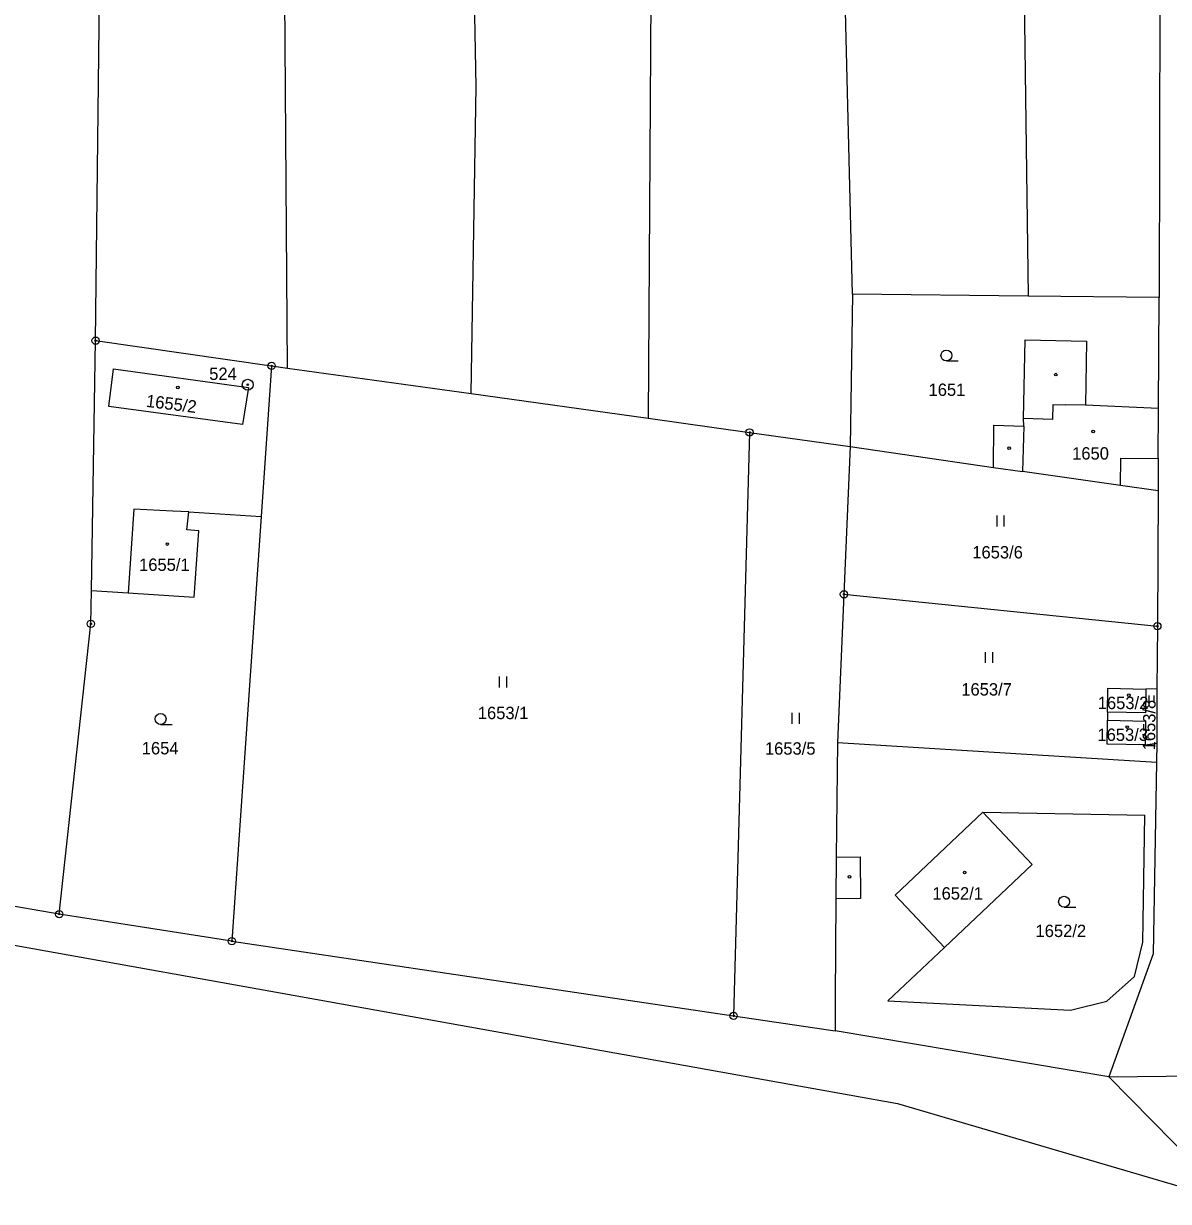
# Model space of a CAD drawing. Extents: x -763296 to -761805, y -1153670 to -1152034.
# Drawn here: x -762912.8 to -762755.5, y -1152914.5 to -1152752.7 of the extents above; entities that cross this region are included whole.
import ezdxf

# ---------------------------------------------------------------- set-up
doc = ezdxf.new("R2010")
doc.units = 0
for name, color, linetype in [('Vrstva 1', 7, 'Continuous'), ('Vrstva 13', 7, 'Continuous'), ('Vrstva 17', 7, 'Continuous'), ('Vrstva 18', 7, 'Continuous'), ('Vrstva 19', 7, 'Continuous'), ('Vrstva 24', 7, 'Continuous'), ('Vrstva 25', 7, 'Continuous'), ('Vrstva 4', 7, 'Continuous'), ('Vrstva 6', 7, 'Continuous')]:
    doc.layers.add(name, color=color, linetype=linetype)

msp = doc.modelspace()

# ---------------------------------------------------------------- linework, layer by layer
at = {"layer": 'Vrstva 1'}
for p, q in [((-762756.58, -1152655.62), (-762756.75, -1152790.35)), ((-762798.9, -1152789.86), (-762799.23, -1152810.81)), ((-762774.75, -1152790.14), (-762798.9, -1152789.86)), ((-762756.75, -1152790.35), (-762774.75, -1152790.14)), ((-762756.85, -1152805.56), (-762756.75, -1152790.35)), ((-762903.46, -1152830.57), (-762902.89, -1152796.26)), ((-762902.89, -1152796.26), (-762878.71, -1152799.72)), ((-762775.39, -1152806.97), (-762775.16, -1152796.14)), ((-762775.16, -1152796.14), (-762766.75, -1152796.35)), ((-762766.75, -1152796.35), (-762766.91, -1152805.13)), ((-762901.08, -1152805.31), (-762900.41, -1152800.13)), ((-762900.41, -1152800.13), (-762881.87, -1152802.7)), ((-762878.71, -1152799.72), (-762880.14, -1152820.4)), ((-762878.71, -1152799.72), (-762876.51, -1152800.03)), ((-762876.51, -1152800.03), (-762851.31, -1152803.53)), ((-762881.87, -1152802.7), (-762882.72, -1152807.79)), ((-762851.31, -1152803.53), (-762826.97, -1152806.92)), ((-762882.72, -1152807.79), (-762901.08, -1152805.31)), ((-762756.85, -1152805.56), (-762766.91, -1152805.13)), ((-762826.97, -1152806.92), (-762813.05, -1152808.86)), ((-762775.38, -1152807.99), (-762775.39, -1152806.97)), ((-762756.9, -1152812.44), (-762756.85, -1152805.56)), ((-762779.53, -1152813.66), (-762779.47, -1152807.88)), ((-762779.47, -1152807.88), (-762775.38, -1152807.99)), ((-762813.05, -1152808.86), (-762815.24, -1152888.99)), ((-762813.05, -1152808.86), (-762799.23, -1152810.81)), ((-762799.23, -1152810.81), (-762800.08, -1152831.1)), ((-762799.23, -1152810.81), (-762779.53, -1152813.66)), ((-762756.9, -1152812.44), (-762756.93, -1152816.89)), ((-762779.53, -1152813.66), (-762775.55, -1152814.21)), ((-762762.09, -1152816.15), (-762775.55, -1152814.21)), ((-762756.93, -1152816.89), (-762762.09, -1152816.15)), ((-762756.93, -1152816.89), (-762757.02, -1152835.47)), ((-762890.36, -1152822.25), (-762890.1, -1152819.76)), ((-762890.1, -1152819.76), (-762880.14, -1152820.4)), ((-762880.14, -1152820.4), (-762884.17, -1152878.73)), ((-762888.71, -1152822.36), (-762890.36, -1152822.25)), ((-762889.33, -1152831.49), (-762888.71, -1152822.36)), ((-762903.54, -1152835.16), (-762903.46, -1152830.57)), ((-762903.46, -1152830.57), (-762898.43, -1152830.91)), ((-762898.43, -1152830.91), (-762889.33, -1152831.49)), ((-762800.08, -1152831.1), (-762800.95, -1152851.46)), ((-762800.08, -1152831.1), (-762757.02, -1152835.47)), ((-762907.88, -1152875.02), (-762903.54, -1152835.16)), ((-762757.02, -1152835.47), (-762757.07, -1152844.07)), ((-762763.87, -1152847.27), (-762763.82, -1152843.98)), ((-762763.82, -1152843.98), (-762758.6, -1152844.12)), ((-762758.6, -1152844.12), (-762758.66, -1152847.39)), ((-762757.07, -1152844.07), (-762758.6, -1152844.12)), ((-762757.07, -1152844.07), (-762757.11, -1152851.54)), ((-762763.87, -1152847.27), (-762763.88, -1152848.38)), ((-762758.66, -1152847.39), (-762763.87, -1152847.27)), ((-762763.93, -1152851.67), (-762763.88, -1152848.38)), ((-762763.88, -1152848.38), (-762758.65, -1152848.51)), ((-762758.65, -1152848.51), (-762758.7, -1152851.79)), ((-762800.95, -1152851.46), (-762801.13, -1152867.18)), ((-762800.95, -1152851.46), (-762757.12, -1152854.17)), ((-762758.7, -1152851.79), (-762763.93, -1152851.67)), ((-762758.7, -1152851.79), (-762757.11, -1152851.54)), ((-762757.11, -1152851.54), (-762757.12, -1152854.17)), ((-762757.12, -1152854.17), (-762757.58, -1152880.46)), ((-762780.99, -1152861.02), (-762774.2, -1152868.19)), ((-762780.99, -1152861.02), (-762758.75, -1152861.44)), ((-762759, -1152878.87), (-762758.75, -1152861.44)), ((-762801.13, -1152867.18), (-762801.17, -1152872.9)), ((-762774.2, -1152868.19), (-762786.25, -1152879.59)), ((-762907.88, -1152875.02), (-762921.7, -1152872.64)), ((-762801.17, -1152872.9), (-762801.28, -1152886.59)), ((-762884.17, -1152878.73), (-762907.88, -1152875.02)), ((-762884.17, -1152878.73), (-762815.24, -1152888.99)), ((-762786.25, -1152879.59), (-762794.03, -1152886.95)), ((-762760.18, -1152883.57), (-762759, -1152878.87)), ((-762757.58, -1152880.46), (-762763.69, -1152897.37)), ((-762763.95, -1152886.97), (-762760.18, -1152883.57)), ((-762801.28, -1152886.59), (-762801.3, -1152891.07)), ((-762794.03, -1152886.95), (-762768.97, -1152888.21)), ((-762768.97, -1152888.21), (-762763.95, -1152886.97)), ((-762815.24, -1152888.99), (-762801.3, -1152891.07)), ((-762763.69, -1152897.37), (-762801.3, -1152891.07)), ((-762763.69, -1152897.37), (-762739.05, -1152897.03))]:
    msp.add_line(p, q, dxfattribs=at)
at = {"layer": 'Vrstva 13'}
for p, q in [((-762956.53, -1152871.69), (-762792.7, -1152901.01)), ((-762792.7, -1152901.01), (-762746.86, -1152914.48))]:
    msp.add_line(p, q, dxfattribs=at)
at = {"layer": 'Vrstva 24'}
for centre, radius in [((-762902.89, -1152796.26), 0.5), ((-762902.89, -1152796.26), 0.1), ((-762878.71, -1152799.72), 0.5), ((-762878.71, -1152799.72), 0.1), ((-762881.99, -1152802.31), 0.75), ((-762881.99, -1152802.31), 0.1), ((-762813.05, -1152808.86), 0.5), ((-762813.05, -1152808.86), 0.1), ((-762800.08, -1152831.1), 0.5), ((-762800.08, -1152831.1), 0.1), ((-762903.54, -1152835.16), 0.5), ((-762903.54, -1152835.16), 0.1), ((-762757.02, -1152835.47), 0.5), ((-762757.02, -1152835.47), 0.1), ((-762907.88, -1152875.02), 0.5), ((-762907.88, -1152875.02), 0.1), ((-762884.17, -1152878.73), 0.5), ((-762884.17, -1152878.73), 0.1), ((-762815.24, -1152888.99), 0.5), ((-762815.24, -1152888.99), 0.1)]:
    msp.add_circle(centre, radius, dxfattribs=at)
at = {"layer": 'Vrstva 25'}
for p, q in [((-762786, -1152799.05), (-762784.4, -1152799.05)), ((-762779.05, -1152821.78), (-762779.05, -1152820.28)), ((-762778.05, -1152821.78), (-762778.05, -1152820.28)), ((-762780.64, -1152840.52), (-762780.64, -1152839.02)), ((-762779.64, -1152840.52), (-762779.64, -1152839.02)), ((-762847.41, -1152843.9), (-762847.41, -1152842.4)), ((-762846.41, -1152843.9), (-762846.41, -1152842.4)), ((-762758.125, -1152846.02), (-762758.125, -1152845.015)), ((-762757.455, -1152846.02), (-762757.455, -1152845.015)), ((-762807.19, -1152848.88), (-762807.19, -1152847.38)), ((-762806.19, -1152848.88), (-762806.19, -1152847.38)), ((-762893.96, -1152848.97), (-762892.36, -1152848.97)), ((-762769.84, -1152874.07), (-762768.24, -1152874.07))]:
    msp.add_line(p, q, dxfattribs=at)
for centre, radius in [((-762786, -1152798.3), 0.75), ((-762770.98, -1152800.92), 0.175), ((-762891.59, -1152802.69), 0.175), ((-762765.83, -1152808.74), 0.175), ((-762777.37, -1152811.03), 0.175), ((-762893.04, -1152824.2), 0.175), ((-762760.93, -1152844.94), 0.175), ((-762893.96, -1152848.22), 0.75), ((-762761.17, -1152849.33), 0.175), ((-762799.32, -1152869.89), 0.175), ((-762783.5, -1152869.31), 0.175), ((-762769.84, -1152873.32), 0.75)]:
    msp.add_circle(centre, radius, dxfattribs=at)
at = {"layer": 'Vrstva 4'}
for p, q in [((-762771.39, -1152807.1), (-762771.32, -1152805.03)), ((-762771.32, -1152805.03), (-762769.68, -1152805.07)), ((-762766.91, -1152805.13), (-762769.68, -1152805.07)), ((-762771.39, -1152807.1), (-762775.39, -1152806.97)), ((-762775.38, -1152807.99), (-762775.55, -1152814.21)), ((-762762.09, -1152816.15), (-762762.05, -1152812.4)), ((-762762.05, -1152812.4), (-762756.9, -1152812.44)), ((-762897.66, -1152819.4), (-762898.43, -1152830.91)), ((-762892.3, -1152819.66), (-762897.66, -1152819.4)), ((-762890.1, -1152819.76), (-762892.3, -1152819.66)), ((-762780.99, -1152861.02), (-762793.02, -1152872.43)), ((-762801.13, -1152867.18), (-762797.86, -1152867.16)), ((-762797.86, -1152867.16), (-762797.82, -1152872.86)), ((-762797.82, -1152872.86), (-762801.17, -1152872.9)), ((-762793.02, -1152872.43), (-762786.25, -1152879.59))]:
    msp.add_line(p, q, dxfattribs=at)
at = {"layer": 'Vrstva 6'}
for p, q in [((-762776.51, -1152660.99), (-762774.75, -1152790.14)), ((-762798.9, -1152789.86), (-762801.85, -1152672.85)), ((-762850.61, -1152761.35), (-762851.61, -1152707.93)), ((-762876.51, -1152800.03), (-762877.08, -1152720.29)), ((-762902.89, -1152796.26), (-762902.21, -1152735.88)), ((-762826.51, -1152736.89), (-762826.97, -1152806.92)), ((-762851.31, -1152803.53), (-762850.61, -1152761.35)), ((-762746.86, -1152914.48), (-762763.69, -1152897.37))]:
    msp.add_line(p, q, dxfattribs=at)

# ---------------------------------------------------------------- texts
at = {"layer": 'Vrstva 17'}
msp.add_text('524', height=1.7, dxfattribs=at).set_placement((-762887.284, -1152801.66))
at = {"layer": 'Vrstva 18'}
for s, p in [('1651', (-762788.454, -1152803.85)), ('1653/6', (-762782.448, -1152826.17)), ('1653/7', (-762783.958, -1152845)), ('1653/1', (-762850.38, -1152848.24)), ('1654', (-762896.552, -1152853.08)), ('1653/5', (-762810.935, -1152853.12)), ('1652/2', (-762773.759, -1152878.17))]:
    msp.add_text(s, height=1.7, dxfattribs=at).set_placement(p)
msp.add_text('1653/8', height=1.7, rotation=89.49601, dxfattribs=at).set_placement((-762757.325, -1152852.538))
at = {"layer": 'Vrstva 19'}
msp.add_text('1655/2', height=1.7, rotation=352.88471, dxfattribs=at).set_placement((-762896.031, -1152805.342))
for s, p in [('1650', (-762768.729, -1152812.59)), ('1655/1', (-762896.92, -1152827.88)), ('1653/2', (-762765.212, -1152846.86)), ('1653/3', (-762765.255, -1152851.23)), ('1652/1', (-762787.927, -1152873.02))]:
    msp.add_text(s, height=1.7, dxfattribs=at).set_placement(p)

doc.saveas('drawing.dxf')
